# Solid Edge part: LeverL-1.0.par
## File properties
Author: Wojciech Szerszeń
Template: ISO Metric Part.par
Last saved by: Wojciech Szerszeń
Revision: 5
Application: Solid Edge
Username: Wojciech Szerszeń
Accuracy: 0.99000000000
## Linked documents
Lever.par
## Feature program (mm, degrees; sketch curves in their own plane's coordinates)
part copy "CopiedPart_1"
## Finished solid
Body 1: solid body, 55 faces, 143 edges, 86 vertices.
  Faces by surface: cylinder 21, plane 20, cone 11, spline 2, swept 1
  Edges by curve: line 67, circle 52, intersection 13, curve on surface 10, ellipse 1
Bounding box of the edges (mm; curved faces can reach further): 79.518 x 52.500 x 32.090, from (-41.2824, -52.5, -13.0066) to (38.2357, 0, 19.0829).
Cylindrical faces by radius (mm): R1 x2, R1.2295 x3, R1.7 x1, R2 x1, R4 x1, R5.5 x1, R5.9998 x2, R8.5 x1, R12 x2, R12.0011 x1, R12.0019 x1, R12.0027 x1, R12.003 x1, R12.105 x1, R15 x1, R25 x1
Conical faces (half-angle, radius in mm at the cone's reference point): 45 deg R10.0011 x1, 45 deg R10.0019 x1, 45 deg R10.0027 x1, 45 deg R12 x3, 45 deg R12.0011 x2, 45 deg R12.0027 x1, 45 deg R15.003 x1, 45 deg R17 x1
Planar faces by outward normal: +y 5, -y 6, oblique 9
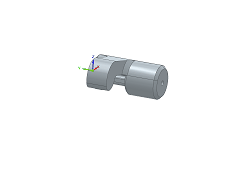
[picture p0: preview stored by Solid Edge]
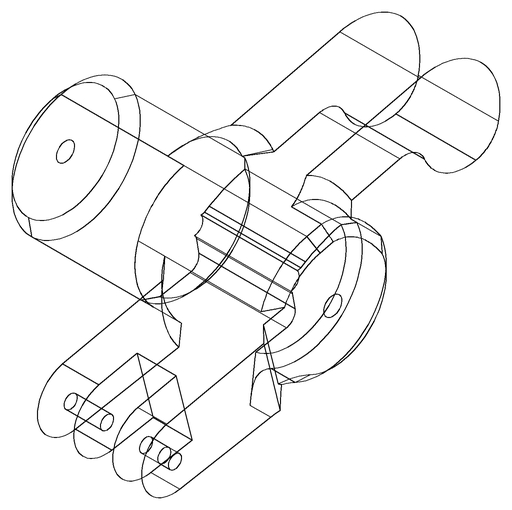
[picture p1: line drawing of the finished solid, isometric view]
